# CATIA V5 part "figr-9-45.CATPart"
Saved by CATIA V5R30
Part number: Part1
Bounding box of the stored display mesh (mm): x -159.661 to 182.627, y -78.048 to 78.048, z 0 to 72.429
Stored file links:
  D:\PROJECTS\CATIA V56R 2020\Resources\Parts File\c09_catia_v5_6r2020_prt\figr-9-45.CATPart
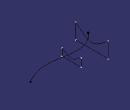
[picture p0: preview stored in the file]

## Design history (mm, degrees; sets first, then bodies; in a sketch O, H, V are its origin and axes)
Body1 (main body)
  Plane1: type Offset, RefPlane yz-plane, Offset 100
  Plane2: type Offset, RefPlane yz-plane, Offset 100, reversed
  Sketch1 on Plane1, origin (100, 0, 0), H (0, 1, 0), V (0, 0, 1)
    point P1 (0, 15.965)
    hyperbola C1
    point P2 (0, 3.0416)
    line L1 (54.8261, 44.8858) -> (54.8261, 0)
    point P5 (54.8261, 0)
    line L2 (-54.8261, 44.8858) -> (-54.8261, 0)
    point P6 (-54.8261, 0)
    line L3 (-54.8261, 0) -> (54.8261, 0)
    coincidence: P1 V, P2 V, P5 H, P6 H
    vertical: L1 V, L2 V
    horizontal: L3 H
  Sketch2 on xy-plane, origin (0, 0, 0), H (1, 0, 0), V (0, 1, 0)
    spline S1 through (-159.6608, -77.1468) (-77.8466, -31.8169) (23.6283, -41.4968) (182.6271, -11.7333)
  Sketch3 on yz-plane, origin (0, 0, 0), H (0, 1, 0), V (0, 0, 1)
    point P1 (0, 18.9787)
    hyperbola C1
    point P2 (0, 2.6681)
    line L1 (48.2237, 37.1764) -> (48.2237, 0)
    point P5 (48.2237, 0)
    line L2 (-43.6563, 34.1546) -> (-43.6563, 0)
    point P6 (-43.6563, 0)
    line L3 (-43.6563, 0) -> (48.2237, 0)
    coincidence: P1 V, P2 V, P5 H, P6 H
    vertical: L1 V, L2 V
    horizontal: L3 H
  Sketch4 on Plane2, origin (-100, 0, 0), H (0, 1, 0), V (0, 0, 1)
    point P1 (0, 140.6052)
    point P2 (0, 41.8972)
    hyperbola C1
    line L1 (78.0478, 72.4293) -> (78.0478, 0)
    point P5 (78.0478, 0)
    line L2 (-78.0478, 72.4293) -> (-78.0478, 0)
    point P6 (-78.0478, 0)
    line L3 (-78.0478, 0) -> (78.0478, 0)
    coincidence: P1 V, P2 V, P5 H, P6 H
    vertical: L1 V, L2 V
    horizontal: L3 H
  Loft1: solid, Sections (Sketch3; Sketch4), Spine Sketch2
